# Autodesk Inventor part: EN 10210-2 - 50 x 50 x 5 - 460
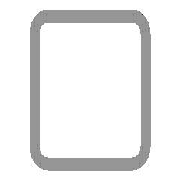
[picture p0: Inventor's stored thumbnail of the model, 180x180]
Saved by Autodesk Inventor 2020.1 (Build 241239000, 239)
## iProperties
_CCFamilyMember: 16
_CCFamilyDisplayName: DIN EN 10210-2 (USAS B17.1 quadratisch) - Rohrleitung — In Klammern angegebene Größen wurden aufgehoben
_FrameMemberDoc: Frame Member File
_Version: 15.0.0
_GetPNFromCC: 1
IsCustomPart: 1
Created: 2019-01
Part Number: EN 10210-2 - 50 x 50 x 5 - 460
Material: Stahl, weich
Description: Rohrleitung
Document SubType Name: Modeling
Standard: DIN
Designer: lutzd
Standard Revision: 2006-07
Standards Organization: DIN
Language: de-DE
Size Designation: 50 x 50 x 5
Categories: <MemberInstance><Categories><Category DisplayName="Profile" InternalName="089c4875-fa83-4c05-b084-43b9cc11f5ed" Mnemonic="GRDR"><CategoryParameter DisplayName="
Stock Number: 50 x 50 x 5
Mass: 3150.31 g
Surface Area: 1575.45 cm^2
Volume: 401.313 cm^3
Density: 7.85 g/cm^3
Appearance: Halbpoliert
G_L: 460,000 mm
G_W: 50,000 mm
G_H: 50,000 mm
DocNumber: ADSK-014082
Folder: .
Dimensions: 50x50x460 mm
Mass: 3,15 kg
+4D0C4AED-00BB-4368-B25E-132D0F83811B+SCHNITTDETAIL1: Schnittwinkel 90,00 grd
Title: Profil-Bauteil
Author: lutzd
Revision Number: -
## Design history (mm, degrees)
node "Startebene"
node "Endebene"
sketch "Skizze"
  geometry: L1 (-25, -17.5)-(-25, 17.5); L2 (-17.5, 25)-(17.5, 25); L3 (25, 17.5)-(25, -17.5); L4 (17.5, -25)-(-17.5, -25); L5 (-15, 20)-(15, 20); L6 (20, 15)-(20, -15); L7 (15, -20)-(-15, -20); L8 (-20, -15)-(-20, 15); L9 (0, 37.175)-(0, -37.175) reference; L10 (-37.175, 0)-(37.175, 0) reference; A1 r 7.5 centre (-17.5, -17.5) between (-25, -17.5) and (-17.5, -25); A2 r 7.5 centre (-17.5, 17.5) between (-17.5, 25) and (-25, 17.5); A3 r 7.5 centre (17.5, 17.5) between (25, 17.5) and (17.5, 25); A4 r 7.5 centre (17.5, -17.5) between (17.5, -25) and (25, -17.5); A5 r 5 centre (-15, -15) between (-20, -15) and (-15, -20); A6 r 5 centre (-15, 15) between (-15, 20) and (-20, 15); A7 r 5 centre (15, 15) between (20, 15) and (15, 20); A8 r 5 centre (15, -15) between (15, -20) and (20, -15)
  constraints: 16 end point, 16 point on circle, 16 tangent, 8 centre point, 6 equal radius, 4 parallel, 2 perpendicular, 2 other
  dimensions: "d7" = 7.5 radius of A1 (= G_IR); "d10" = 50 distance between parallel lines of L2 L4 (= G_H); "d11" = 50 distance between parallel lines of L1 L3 (= G_W); "d12" = 5 distance between parallel lines of L3 L6 (= G_T); "d15" = 25 distance between parallel lines of L2 L10 (= 0.5 x d10); "d16" = 25 distance between parallel lines of L9 L3 (= 0.5 x d11); "d19" = 5 radius of A5 (= G_T); "d20" = 5 distance between parallel lines of L4 L7 (= G_T)
extrude "Körper" new body sketch "Skizze" stored distance "d3" = 460 (= G_L); taper "d4" = 0 deg
node "Driven Length"
  sketch "Sketch3"
    geometry: L1 (0, 0)-(10, 0) reference
    constraints: 2 end point, 1 horizontal
  workplane "Work Plane3"
  sketch "Sketch4"
    geometry: L1 (-2, 25)-(12, 25) reference; L2 (-2, 485)-(12, 485) reference
    dimensions: "d18" = 460 distance between parallel lines of L1 L2 (derived)
workplane "Arbeitsebene4"
feature "Trennen1"
sketch "Skizze5"
  geometry: L1 (0, -35)-(0, 0) reference; L2 (0, -17.5)-(321, -17.5); 3 further points
  constraints: 2 end point, 1 coincident, 1 horizontal, 1 midpoint, 1 point on line
  dimensions: "d21" = 41 distance of point (280, -17.5) point (321, -17.5); "d22" = 280 distance from line of L1 point (280, -17.5)
hole "Bohrung1" sketch "Skizze5" at (321, -17.5), (280, -17.5) diameter "d23" = 6.647; stored, may be unused: countersink angle "d27" = 90 deg, drill point angle "d29" = 118 deg; dims "d24" = 16, "d25" = 4, "d26" = 2, "d28" = 8
body "Solid1"
other parameters: "G_W" = 50 [user parameter; used in 1 equation term], "G_H" = 50 [user parameter; used in 1 equation term], "G_T" = 5 [user parameter; used in 3 equation terms], "G_IR" = 7.5 [user parameter; used in 1 equation term], "G_L" = 460 (= d18) [user parameter; used in 1 equation term], "G_OFFSET_START" = -25 [user parameter; used in 1 equation term], "G_OFFSET_END" = 0 [user parameter; used in 1 equation term], "d13" = 25 (= -G_OFFSET_START), "d14" = 485 (= G_OFFSET_END + B_L), "B_L" = 485 [user parameter; used in 1 equation term], "d17" = 90 deg
